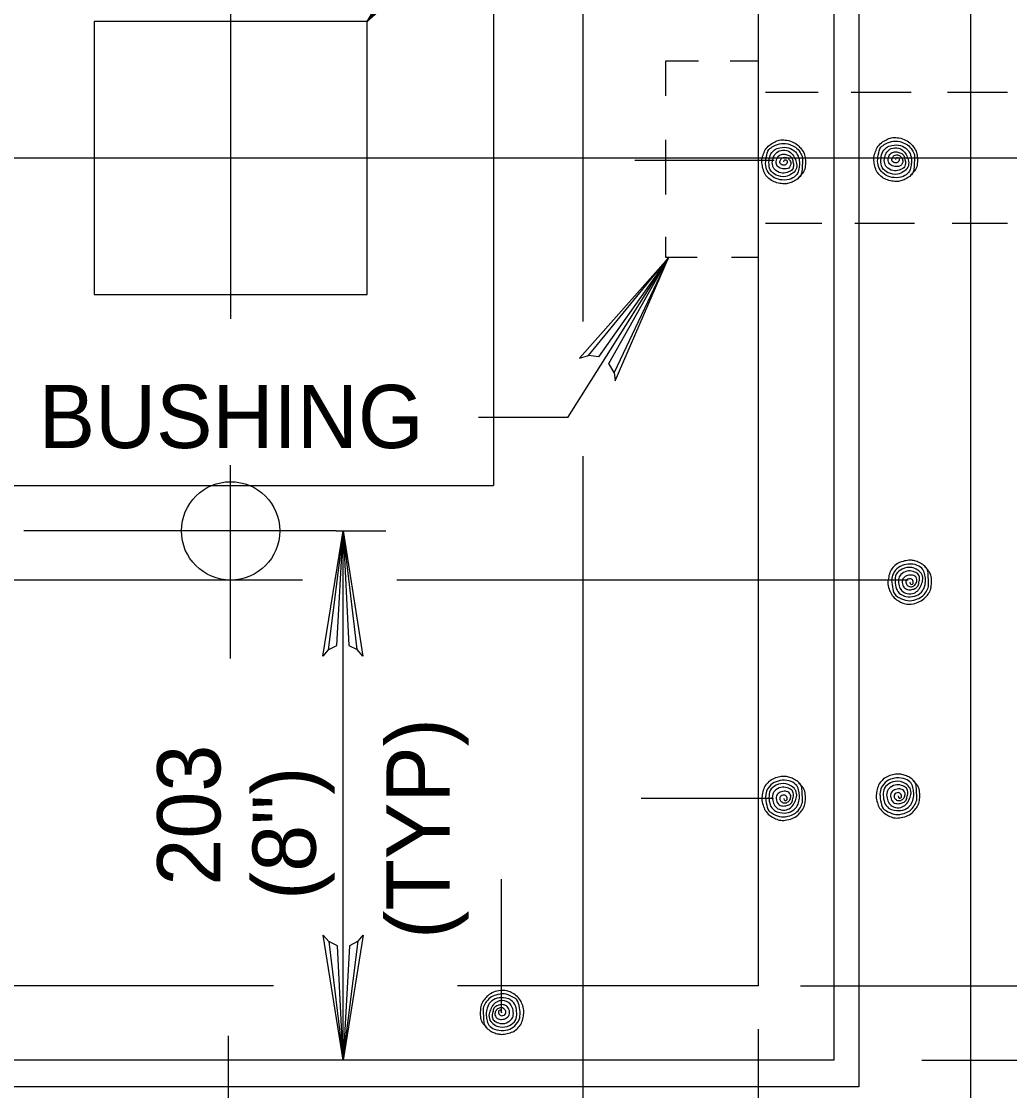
# Model space of a CAD drawing. Extents: x 638455 to 640199, y 298558 to 299152.
# Drawn here: x 639488.2 to 639540.7, y 298956 to 299012.9 of the extents above; entities that cross this region are included whole.
import ezdxf

# ---------------------------------------------------------------- set-up
doc = ezdxf.new("R2010")
doc.units = 0
for name, color, linetype in [('1', 7, 'Continuous'), ('2', 7, 'Continuous'), ('3', 7, 'Continuous')]:
    doc.layers.add(name, color=color, linetype=linetype)

msp = doc.modelspace()

# ---------------------------------------------------------------- linework, layer by layer
at = {"layer": '1'}
msp.add_lwpolyline([(639519.71, 298994.193), (639519.436, 298994.664), (639522.61, 299000.289), (639519.71, 298994.193), (639519.772, 298993.745), (639522.61, 299000.289), (639518.87, 298995.032), (639518.339, 298995.093), (639522.61, 299000.289), (639517.874, 298994.96), (639518.339, 298995.093)], dxfattribs=at)
at = {"layer": '2'}
for p, q in [((639499.316, 299069.23), (639499.316, 298997.046)), ((639538.663, 299061.884), (639538.663, 298949.406)), ((639518.052, 299058.705), (639518.052, 298996.906)), ((639532.731, 299055.006), (639532.731, 298956.209)), ((639531.389, 299053.726), (639531.389, 298957.614)), ((639527.364, 299049.639), (639527.364, 298961.576)), ((639513.286, 299023.031), (639513.286, 298988.183)), ((639522.467, 299008.908), (639522.467, 299010.762)), ((639522.467, 299010.762), (639524.195, 299010.762)), ((639525.881, 299010.762), (639527.364, 299010.762)), ((639530.566, 299009.092), (639527.764, 299009.092)), ((639535.5, 299009.092), (639532.315, 299009.092)), ((639540.636, 299009.092), (639537.437, 299009.092)), ((639522.467, 299003.654), (639522.467, 299006.562)), ((639438.428, 299005.607), (639589.806, 299005.607)), ((639520.809, 299005.482), (639528.216, 299005.482)), ((639530.753, 299002.123), (639527.764, 299002.123)), ((639535.688, 299002.123), (639532.502, 299002.123)), ((639540.636, 299002.123), (639537.686, 299002.123)), ((639522.467, 299000.308), (639522.467, 299001.403)), ((639524.133, 299000.308), (639522.467, 299000.308)), ((639527.364, 299000.308), (639525.944, 299000.308)), ((639517.25, 298991.796), (639512.492, 298991.796)), ((639518.052, 298989.738), (639518.052, 298951.846)), ((639499.316, 298978.985), (639499.316, 298989.26)), ((639373.945, 298988.183), (639513.286, 298988.183)), ((639504.935, 298985.77), (639488.31, 298985.77)), ((639504.935, 298985.77), (639507.562, 298985.77)), ((639505.295, 298957.614), (639505.295, 298985.77)), ((639463.713, 298983.172), (639503.146, 298983.172)), ((639508.161, 298983.172), (639535.345, 298983.172)), ((639528.179, 298971.529), (639521.144, 298971.529)), ((639513.711, 298967.253), (639513.711, 298960.129)), ((639501.592, 298961.576), (639471.267, 298961.576)), ((639527.364, 298961.576), (639511.383, 298961.576)), ((639529.623, 298961.576), (639584.074, 298961.576)), ((639527.364, 298959.272), (639527.364, 298909.034)), ((639499.184, 298958.913), (639499.184, 298936.341)), ((639531.389, 298957.614), (639467.242, 298957.614)), ((639536.071, 298957.614), (639584.074, 298957.614)), ((639532.731, 298956.209), (639465.9, 298956.209))]:
    msp.add_line(p, q, dxfattribs=at)
for points in [[(639511.228, 299017.233), (639510.725, 299017.34), (639506.576, 299012.867), (639511.228, 299017.233), (639511.648, 299017.302), (639506.576, 299012.867), (639510.232, 299017.746), (639510.024, 299018.205), (639506.576, 299012.867), (639510.01, 299018.662), (639510.024, 299018.205)], [(639517.25, 298991.796), (639522.61, 299000.289)], [(639504.499, 298979.439), (639504.958, 298979.674), (639505.295, 298985.77), (639504.499, 298979.439), (639504.224, 298979.113), (639505.295, 298985.77), (639505.597, 298979.68), (639506.05, 298979.459), (639505.295, 298985.77), (639506.352, 298979.113), (639506.05, 298979.459)], [(639506.091, 298963.942), (639505.632, 298963.707), (639505.295, 298957.614), (639506.091, 298963.942), (639506.367, 298964.267), (639505.295, 298957.614), (639504.993, 298963.701), (639504.54, 298963.924), (639505.295, 298957.614), (639504.238, 298964.267), (639504.54, 298963.924)]]:
    msp.add_lwpolyline(points, dxfattribs=at)
msp.add_lwpolyline([(639492.056, 298998.347), (639506.576, 298998.347), (639506.576, 299012.867), (639492.056, 299012.867)], close=True, dxfattribs=at)
msp.add_circle((639499.315, 298985.77), 2.614, dxfattribs=at)
for points in [[(639528.732, 299005.391), (639528.79, 299005.507), (639528.88, 299005.493), (639528.897, 299005.31), (639528.735, 299005.211), (639528.54, 299005.31), (639528.549, 299005.493), (639528.657, 299005.606), (639528.88, 299005.623), (639529.031, 299005.507), (639529.107, 299005.319), (639528.993, 299005.069), (639528.752, 299005.017), (639528.485, 299005.098), (639528.343, 299005.266), (639528.36, 299005.551), (639528.494, 299005.734), (639528.735, 299005.801), (639528.95, 299005.757), (639529.127, 299005.65), (639529.205, 299005.464), (639529.249, 299005.223), (639529.197, 299004.999), (639528.985, 299004.857), (639528.665, 299004.793), (639528.317, 299004.935), (639528.143, 299005.176), (639528.143, 299005.507), (639528.256, 299005.789), (639528.494, 299005.975), (639528.88, 299005.998), (639529.15, 299005.847), (639529.316, 299005.583), (639529.414, 299005.31), (639529.371, 299004.982), (639529.15, 299004.75), (639528.834, 299004.616), (639528.331, 299004.694), (639528.012, 299004.973), (639527.945, 299005.356), (639528.012, 299005.734), (639528.232, 299006.03), (639528.526, 299006.149), (639528.985, 299006.14), (639529.348, 299005.931), (639529.522, 299005.623), (639529.565, 299005.298), (639529.534, 299005.017), (639529.423, 299004.715), (639529.127, 299004.5), (639528.648, 299004.433), (639528.218, 299004.552), (639527.901, 299004.848), (639527.774, 299005.194), (639527.803, 299005.635), (639527.945, 299006.051), (639528.186, 299006.225), (639528.61, 299006.376), (639529.051, 299006.315), (639529.359, 299006.172), (639529.597, 299005.899), (639529.722, 299005.615), (639529.722, 299005.31), (639529.708, 299004.982), (639529.632, 299004.674), (639529.475, 299004.5), (639529.234, 299004.349), (639528.993, 299004.258), (639528.752, 299004.224), (639528.45, 299004.267), (639528.143, 299004.366), (639527.878, 299004.561), (639527.698, 299004.81), (639527.608, 299005.124), (639527.562, 299005.417), (639527.629, 299005.757), (639527.75, 299006.03), (639527.968, 299006.28), (639528.232, 299006.448), (639528.494, 299006.547), (639528.808, 299006.556), (639529.174, 299006.466), (639529.475, 299006.28), (639529.664, 299006.082), (639529.821, 299005.833), (639529.873, 299005.568), (639529.882, 299005.266), (639529.821, 299004.935), (639529.722, 299004.784), (639529.522, 299004.561)], [(639534.687, 299005.516), (639534.745, 299005.632), (639534.835, 299005.618), (639534.852, 299005.435), (639534.69, 299005.336), (639534.495, 299005.435), (639534.504, 299005.618), (639534.611, 299005.731), (639534.835, 299005.748), (639534.986, 299005.632), (639535.061, 299005.444), (639534.948, 299005.194), (639534.707, 299005.142), (639534.44, 299005.223), (639534.298, 299005.391), (639534.315, 299005.676), (639534.448, 299005.859), (639534.69, 299005.926), (639534.905, 299005.882), (639535.082, 299005.775), (639535.16, 299005.589), (639535.204, 299005.348), (639535.151, 299005.124), (639534.939, 299004.982), (639534.62, 299004.918), (639534.271, 299005.06), (639534.097, 299005.301), (639534.097, 299005.632), (639534.21, 299005.914), (639534.448, 299006.1), (639534.835, 299006.123), (639535.105, 299005.972), (639535.27, 299005.708), (639535.369, 299005.435), (639535.326, 299005.107), (639535.105, 299004.875), (639534.788, 299004.741), (639534.286, 299004.819), (639533.967, 299005.098), (639533.9, 299005.481), (639533.967, 299005.859), (639534.187, 299006.155), (639534.481, 299006.274), (639534.939, 299006.265), (639535.302, 299006.056), (639535.477, 299005.748), (639535.52, 299005.423), (639535.488, 299005.142), (639535.378, 299004.84), (639535.082, 299004.625), (639534.602, 299004.558), (639534.173, 299004.677), (639533.856, 299004.973), (639533.729, 299005.319), (639533.758, 299005.76), (639533.9, 299006.176), (639534.141, 299006.35), (639534.565, 299006.501), (639535.006, 299006.44), (639535.314, 299006.297), (639535.552, 299006.024), (639535.677, 299005.74), (639535.677, 299005.435), (639535.662, 299005.107), (639535.587, 299004.799), (639535.43, 299004.625), (639535.189, 299004.474), (639534.948, 299004.383), (639534.707, 299004.349), (639534.405, 299004.392), (639534.097, 299004.491), (639533.833, 299004.686), (639533.653, 299004.935), (639533.563, 299005.249), (639533.517, 299005.542), (639533.583, 299005.882), (639533.705, 299006.155), (639533.923, 299006.405), (639534.187, 299006.573), (639534.448, 299006.672), (639534.762, 299006.681), (639535.128, 299006.591), (639535.43, 299006.405), (639535.619, 299006.207), (639535.776, 299005.958), (639535.828, 299005.693), (639535.837, 299005.391), (639535.776, 299005.06), (639535.677, 299004.909), (639535.477, 299004.686)], [(639535.434, 298983.044), (639535.492, 298982.928), (639535.581, 298982.943), (639535.599, 298983.125), (639535.439, 298983.221), (639535.242, 298983.125), (639535.25, 298982.943), (639535.358, 298982.829), (639535.581, 298982.812), (639535.732, 298982.928), (639535.808, 298983.117), (639535.698, 298983.366), (639535.457, 298983.419), (639535.19, 298983.337), (639535.047, 298983.169), (639535.065, 298982.884), (639535.198, 298982.701), (639535.439, 298982.635), (639535.654, 298982.678), (639535.831, 298982.785), (639535.907, 298982.972), (639535.953, 298983.212), (639535.898, 298983.436), (639535.689, 298983.578), (639535.366, 298983.642), (639535.021, 298983.5), (639534.847, 298983.259), (639534.847, 298982.928), (639534.957, 298982.646), (639535.198, 298982.46), (639535.581, 298982.437), (639535.855, 298982.588), (639536.02, 298982.852), (639536.116, 298983.125), (639536.072, 298983.453), (639535.855, 298983.686), (639535.538, 298983.819), (639535.033, 298983.741), (639534.716, 298983.462), (639534.649, 298983.079), (639534.716, 298982.701), (639534.934, 298982.405), (639535.23, 298982.286), (639535.689, 298982.295), (639536.049, 298982.504), (639536.223, 298982.812), (639536.27, 298983.137), (639536.238, 298983.419), (639536.125, 298983.72), (639535.831, 298983.936), (639535.349, 298984.002), (639534.923, 298983.883), (639534.606, 298983.587), (639534.475, 298983.241), (639534.507, 298982.8), (639534.649, 298982.385), (639534.89, 298982.21), (639535.314, 298982.059), (639535.756, 298982.121), (639536.064, 298982.263), (639536.299, 298982.536), (639536.424, 298982.82), (639536.424, 298983.125), (639536.412, 298983.453), (639536.337, 298983.761), (639536.18, 298983.936), (639535.939, 298984.087), (639535.698, 298984.177), (639535.457, 298984.212), (639535.155, 298984.168), (639534.847, 298984.069), (639534.582, 298983.874), (639534.4, 298983.625), (639534.31, 298983.311), (639534.266, 298983.018), (639534.333, 298982.678), (639534.452, 298982.405), (639534.673, 298982.155), (639534.934, 298981.987), (639535.198, 298981.888), (639535.512, 298981.88), (639535.875, 298981.97), (639536.18, 298982.155), (639536.366, 298982.353), (639536.523, 298982.603), (639536.578, 298982.867), (639536.586, 298983.169), (639536.523, 298983.5), (639536.424, 298983.651), (639536.223, 298983.874)], [(639528.73, 298971.545), (639528.788, 298971.429), (639528.877, 298971.444), (639528.895, 298971.626), (639528.735, 298971.722), (639528.538, 298971.626), (639528.546, 298971.444), (639528.654, 298971.33), (639528.877, 298971.313), (639529.028, 298971.429), (639529.104, 298971.618), (639528.994, 298971.867), (639528.753, 298971.92), (639528.486, 298971.838), (639528.343, 298971.67), (639528.361, 298971.385), (639528.494, 298971.202), (639528.735, 298971.136), (639528.95, 298971.179), (639529.127, 298971.286), (639529.203, 298971.473), (639529.249, 298971.713), (639529.194, 298971.937), (639528.985, 298972.079), (639528.662, 298972.143), (639528.317, 298972.001), (639528.143, 298971.76), (639528.143, 298971.429), (639528.253, 298971.147), (639528.494, 298970.961), (639528.877, 298970.938), (639529.151, 298971.089), (639529.316, 298971.353), (639529.412, 298971.626), (639529.368, 298971.954), (639529.151, 298972.187), (639528.834, 298972.32), (639528.329, 298972.242), (639528.012, 298971.963), (639527.945, 298971.58), (639528.012, 298971.202), (639528.23, 298970.906), (639528.526, 298970.787), (639528.985, 298970.796), (639529.345, 298971.005), (639529.519, 298971.313), (639529.566, 298971.638), (639529.534, 298971.92), (639529.421, 298972.221), (639529.127, 298972.437), (639528.645, 298972.503), (639528.219, 298972.384), (639527.902, 298972.088), (639527.771, 298971.742), (639527.803, 298971.301), (639527.945, 298970.886), (639528.186, 298970.711), (639528.61, 298970.56), (639529.052, 298970.622), (639529.36, 298970.764), (639529.595, 298971.037), (639529.72, 298971.321), (639529.72, 298971.626), (639529.708, 298971.954), (639529.633, 298972.262), (639529.476, 298972.437), (639529.235, 298972.588), (639528.994, 298972.678), (639528.753, 298972.713), (639528.451, 298972.669), (639528.143, 298972.57), (639527.878, 298972.375), (639527.696, 298972.126), (639527.606, 298971.812), (639527.562, 298971.519), (639527.629, 298971.179), (639527.748, 298970.906), (639527.969, 298970.656), (639528.23, 298970.488), (639528.494, 298970.389), (639528.808, 298970.381), (639529.171, 298970.471), (639529.476, 298970.656), (639529.662, 298970.854), (639529.819, 298971.104), (639529.874, 298971.368), (639529.882, 298971.67), (639529.819, 298972.001), (639529.72, 298972.152), (639529.519, 298972.375)], [(639534.809, 298971.67), (639534.867, 298971.554), (639534.957, 298971.569), (639534.974, 298971.751), (639534.815, 298971.847), (639534.617, 298971.751), (639534.626, 298971.569), (639534.734, 298971.455), (639534.957, 298971.438), (639535.108, 298971.554), (639535.184, 298971.743), (639535.073, 298971.992), (639534.832, 298972.045), (639534.565, 298971.963), (639534.423, 298971.795), (639534.44, 298971.51), (639534.574, 298971.327), (639534.815, 298971.261), (639535.03, 298971.304), (639535.207, 298971.411), (639535.282, 298971.598), (639535.329, 298971.838), (639535.274, 298972.062), (639535.065, 298972.204), (639534.742, 298972.268), (639534.397, 298972.126), (639534.222, 298971.885), (639534.222, 298971.554), (639534.333, 298971.272), (639534.574, 298971.086), (639534.957, 298971.063), (639535.23, 298971.214), (639535.395, 298971.478), (639535.491, 298971.751), (639535.448, 298972.079), (639535.23, 298972.312), (639534.914, 298972.445), (639534.408, 298972.367), (639534.092, 298972.088), (639534.025, 298971.705), (639534.092, 298971.327), (639534.309, 298971.031), (639534.606, 298970.912), (639535.065, 298970.921), (639535.424, 298971.13), (639535.599, 298971.438), (639535.645, 298971.763), (639535.613, 298972.045), (639535.5, 298972.346), (639535.207, 298972.562), (639534.725, 298972.628), (639534.298, 298972.509), (639533.981, 298972.213), (639533.851, 298971.867), (639533.883, 298971.426), (639534.025, 298971.011), (639534.266, 298970.836), (639534.69, 298970.685), (639535.131, 298970.747), (639535.439, 298970.889), (639535.674, 298971.162), (639535.799, 298971.446), (639535.799, 298971.751), (639535.787, 298972.079), (639535.712, 298972.387), (639535.555, 298972.562), (639535.314, 298972.713), (639535.073, 298972.803), (639534.832, 298972.838), (639534.53, 298972.794), (639534.222, 298972.695), (639533.958, 298972.5), (639533.775, 298972.251), (639533.685, 298971.937), (639533.642, 298971.644), (639533.708, 298971.304), (639533.827, 298971.031), (639534.048, 298970.781), (639534.309, 298970.613), (639534.574, 298970.514), (639534.887, 298970.506), (639535.25, 298970.596), (639535.555, 298970.781), (639535.741, 298970.979), (639535.898, 298971.229), (639535.953, 298971.493), (639535.962, 298971.795), (639535.898, 298972.126), (639535.799, 298972.277), (639535.599, 298972.5)], [(639513.743, 298960.16), (639513.685, 298960.276), (639513.598, 298960.264), (639513.58, 298960.082), (639513.74, 298959.983), (639513.935, 298960.082), (639513.926, 298960.264), (639513.818, 298960.375), (639513.598, 298960.393), (639513.444, 298960.276), (639513.368, 298960.09), (639513.481, 298959.841), (639513.723, 298959.785), (639513.99, 298959.867), (639514.132, 298960.035), (639514.115, 298960.32), (639513.981, 298960.503), (639513.74, 298960.572), (639513.525, 298960.526), (639513.348, 298960.418), (639513.272, 298960.233), (639513.226, 298959.992), (639513.281, 298959.768), (639513.49, 298959.626), (639513.81, 298959.562), (639514.158, 298959.707), (639514.332, 298959.945), (639514.332, 298960.276), (639514.222, 298960.558), (639513.981, 298960.744), (639513.598, 298960.767), (639513.325, 298960.616), (639513.159, 298960.352), (639513.06, 298960.082), (639513.107, 298959.751), (639513.325, 298959.518), (639513.641, 298959.385), (639514.146, 298959.466), (639514.463, 298959.742), (639514.53, 298960.125), (639514.463, 298960.503), (639514.242, 298960.799), (639513.949, 298960.918), (639513.49, 298960.91), (639513.127, 298960.7), (639512.956, 298960.393), (639512.909, 298960.067), (639512.941, 298959.785), (639513.052, 298959.483), (639513.348, 298959.269), (639513.83, 298959.202), (639514.257, 298959.321), (639514.574, 298959.617), (639514.704, 298959.966), (639514.672, 298960.407), (639514.53, 298960.822), (639514.289, 298960.994), (639513.865, 298961.147), (639513.423, 298961.084), (639513.115, 298960.941), (639512.877, 298960.668), (639512.752, 298960.384), (639512.752, 298960.082), (639512.767, 298959.751), (639512.843, 298959.443), (639512.999, 298959.269), (639513.24, 298959.117), (639513.481, 298959.028), (639513.723, 298958.993), (639514.025, 298959.036), (639514.332, 298959.135), (639514.597, 298959.329), (639514.779, 298959.579), (639514.867, 298959.893), (639514.913, 298960.186), (639514.846, 298960.526), (639514.724, 298960.799), (639514.507, 298961.049), (639514.242, 298961.217), (639513.981, 298961.316), (639513.667, 298961.325), (639513.301, 298961.235), (639512.999, 298961.049), (639512.81, 298960.851), (639512.657, 298960.602), (639512.601, 298960.34), (639512.593, 298960.035), (639512.657, 298959.707), (639512.752, 298959.553), (639512.956, 298959.329)]]:
    msp.add_spline(points, degree=3, dxfattribs=at)

# ---------------------------------------------------------------- texts
at = {"layer": '3'}
msp.add_text('BUSHING', height=3.36, dxfattribs=at).set_placement((639489.109, 298990.173))
for s, p in [('(TYP)', (639510.963, 298964.074)), ('203', (639498.77, 298966.902)), ('(8")', (639503.842, 298966.143))]:
    msp.add_text(s, height=3.36, rotation=90, dxfattribs=at).set_placement(p)

doc.saveas('drawing.dxf')
